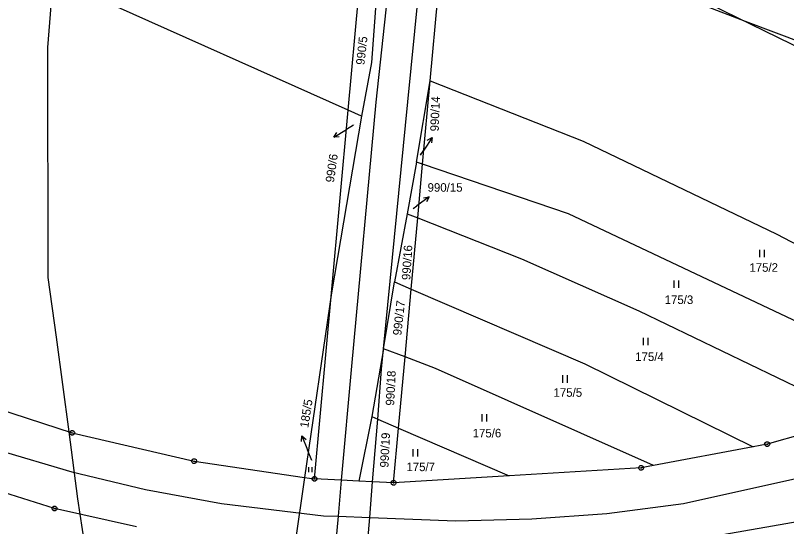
# Model space of a CAD drawing. Extents: x -755359 to -754474, y -1162585 to -1161655.
# Drawn here: x -755164.4 to -755011, y -1162245.9 to -1162144.3 of the extents above; entities that cross this region are included whole.
import ezdxf

# ---------------------------------------------------------------- set-up
doc = ezdxf.new("R2010")
doc.units = 0
for name, color, linetype in [('Vrstva 1', 7, 'Continuous'), ('Vrstva 11', 7, 'Continuous'), ('Vrstva 2', 7, 'Continuous'), ('Vrstva 3', 7, 'Continuous'), ('Vrstva 4', 7, 'Continuous'), ('Vrstva 6', 7, 'Continuous'), ('Vrstva 7', 7, 'Continuous'), ('Vrstva 8', 7, 'Continuous')]:
    doc.layers.add(name, color=color, linetype=linetype)

msp = doc.modelspace()

# ---------------------------------------------------------------- linework, layer by layer
at = {"layer": 'Vrstva 1'}
for p, q in [((-755081.87, -1162157.32), (-755078.18, -1162116.73)), ((-755078.18, -1162116.73), (-754923.5, -1162192.2)), ((-755098.17, -1162163.16), (-755171.47, -1162130.42)), ((-755098.17, -1162163.16), (-755095.99, -1162139.26)), ((-755092.6, -1162141.02), (-755093.55, -1162153.72)), ((-755093.55, -1162153.72), (-755095.52, -1162164.34)), ((-755084.59, -1162173.51), (-755081.87, -1162157.32)), ((-755083.38, -1162173.92), (-755081.87, -1162157.32)), ((-755081.87, -1162157.32), (-755051.44, -1162169.33)), ((-755101.49, -1162199.47), (-755098.17, -1162163.16)), ((-755095.52, -1162164.34), (-755098.17, -1162163.16)), ((-755095.52, -1162164.34), (-755101.49, -1162199.47)), ((-755051.44, -1162169.33), (-755012.93, -1162187.79)), ((-755084.59, -1162173.51), (-755086.46, -1162183.76)), ((-755083.38, -1162173.92), (-755084.59, -1162173.51)), ((-755084.35, -1162184.59), (-755083.38, -1162173.92)), ((-755054.32, -1162183.78), (-755083.38, -1162173.92)), ((-755086.46, -1162183.76), (-755088.99, -1162197.29)), ((-755086.46, -1162183.76), (-755084.35, -1162184.59)), ((-755003.14, -1162207.94), (-755054.32, -1162183.78)), ((-755085.64, -1162198.73), (-755084.35, -1162184.59)), ((-755084.35, -1162184.59), (-755063.67, -1162192.69)), ((-755012.93, -1162187.79), (-754964.26, -1162213.49)), ((-755063.67, -1162192.69), (-755040.35, -1162203.08)), ((-755091.13, -1162210.63), (-755088.99, -1162197.29)), ((-755088.99, -1162197.29), (-755085.64, -1162198.73)), ((-755086.87, -1162212.23), (-755085.64, -1162198.73)), ((-755085.64, -1162198.73), (-755051.1, -1162213.59)), ((-755101.49, -1162199.47), (-755106.85, -1162236.16)), ((-755104.87, -1162236.45), (-755101.49, -1162199.47)), ((-755040.35, -1162203.08), (-754996.22, -1162224.35)), ((-755091.13, -1162210.63), (-755093.47, -1162224.09)), ((-755086.87, -1162212.23), (-755091.13, -1162210.63)), ((-755088.15, -1162226.38), (-755086.87, -1162212.23)), ((-755080.8, -1162214.51), (-755086.87, -1162212.23)), ((-755037.41, -1162233.8), (-755080.8, -1162214.51)), ((-755051.1, -1162213.59), (-755017.58, -1162230.07)), ((-755175.66, -1162219.97), (-755153.09, -1162227.31)), ((-755093.47, -1162224.09), (-755096.04, -1162236.88)), ((-755093.47, -1162224.09), (-755092.31, -1162224.59)), ((-755092.31, -1162224.59), (-755088.15, -1162226.38)), ((-754996.22, -1162224.35), (-755014.83, -1162229.55)), ((-755089.14, -1162237.23), (-755088.15, -1162226.38)), ((-755088.15, -1162226.38), (-755066.18, -1162235.85)), ((-755153.09, -1162227.31), (-755128.84, -1162232.93)), ((-755017.58, -1162230.07), (-755037.41, -1162233.8)), ((-755014.83, -1162229.55), (-755017.58, -1162230.07)), ((-755128.84, -1162232.93), (-755106.85, -1162236.16)), ((-755039.91, -1162234.27), (-755066.18, -1162235.85)), ((-755037.41, -1162233.8), (-755039.91, -1162234.27)), ((-755156.59, -1162242.36), (-755179.53, -1162235.08)), ((-755106.85, -1162236.16), (-755108.91, -1162250.29)), ((-755106.85, -1162236.16), (-755104.87, -1162236.45)), ((-755066.18, -1162235.85), (-755089.14, -1162237.23)), ((-755099.55, -1162236.71), (-755104.87, -1162236.45)), ((-755096.04, -1162236.88), (-755099.55, -1162236.71)), ((-755093.31, -1162237.02), (-755096.04, -1162236.88)), ((-755089.14, -1162237.23), (-755093.31, -1162237.02)), ((-755140.31, -1162246.01), (-755156.59, -1162242.36)), ((-755003.23, -1162244.03), (-755013.79, -1162245.86)), ((-755013.79, -1162245.86), (-755036.82, -1162249.84))]:
    msp.add_line(p, q, dxfattribs=at)
at = {"layer": 'Vrstva 11'}
for p, q in [((-755156.92, -1162136.92), (-755157.97, -1162150.73)), ((-755019.15, -1162145.53), (-755027.45, -1162142.39)), ((-755000.49, -1162152.59), (-755019.15, -1162145.53)), ((-755157.97, -1162150.73), (-755157.96, -1162196.43)), ((-755157.96, -1162196.43), (-755156.26, -1162208.28)), ((-755156.26, -1162208.28), (-755153.77, -1162227.09)), ((-755153.77, -1162227.09), (-755152.01, -1162240.45)), ((-755152.01, -1162240.45), (-755151.54, -1162243.49)), ((-755151.54, -1162243.49), (-755148.61, -1162262.46))]:
    msp.add_line(p, q, dxfattribs=at)
at = {"layer": 'Vrstva 3'}
for p, q in [((-755016.38, -1162190.9), (-755016.38, -1162192.4)), ((-755015.38, -1162192.4), (-755015.38, -1162190.9)), ((-755033.38, -1162197.01), (-755033.38, -1162198.51)), ((-755032.38, -1162198.51), (-755032.38, -1162197.01)), ((-755039.5, -1162208.39), (-755039.5, -1162209.89)), ((-755038.5, -1162209.89), (-755038.5, -1162208.39)), ((-755055.53, -1162215.84), (-755055.53, -1162217.34)), ((-755054.53, -1162217.34), (-755054.53, -1162215.84)), ((-755071.62, -1162223.57), (-755071.62, -1162225.07)), ((-755070.62, -1162225.07), (-755070.62, -1162223.57)), ((-755085.31, -1162230.52), (-755085.31, -1162232.02)), ((-755084.31, -1162232.02), (-755084.31, -1162230.52)), ((-755106.045, -1162234.105), (-755106.045, -1162235.11)), ((-755105.375, -1162235.11), (-755105.375, -1162234.105))]:
    msp.add_line(p, q, dxfattribs=at)
at = {"layer": 'Vrstva 4'}
for p, q in [((-755087.37, -1162112.06), (-755092.67, -1162161.58)), ((-755086.32, -1162161.53), (-755081.63, -1162114.72)), ((-755092.67, -1162161.58), (-755097.54, -1162214.06)), ((-755091.13, -1162210.63), (-755086.32, -1162161.53)), ((-755091.52, -1162214.66), (-755091.13, -1162210.63)), ((-755097.54, -1162214.06), (-755099.55, -1162236.71)), ((-755092.31, -1162224.59), (-755091.52, -1162214.66)), ((-755093.31, -1162237.02), (-755092.31, -1162224.59)), ((-755099.55, -1162236.71), (-755100.18, -1162243.88)), ((-755093.88, -1162244.12), (-755093.31, -1162237.02)), ((-755100.18, -1162243.88), (-755100.83, -1162251.16)), ((-755094.25, -1162248.72), (-755093.88, -1162244.12))]:
    msp.add_line(p, q, dxfattribs=at)
at = {"layer": 'Vrstva 6'}
for p, q in [((-755168.39, -1162230.54), (-755153.14, -1162235.03)), ((-755031.48, -1162241.38), (-754992.46, -1162232.61)), ((-755153.14, -1162235.03), (-755138.48, -1162238.56)), ((-755138.48, -1162238.56), (-755123.39, -1162241.32)), ((-755123.39, -1162241.32), (-755103.11, -1162243.77)), ((-755046.74, -1162243.36), (-755031.48, -1162241.38)), ((-755103.11, -1162243.77), (-755100.18, -1162243.88)), ((-755100.18, -1162243.88), (-755093.88, -1162244.12)), ((-755061.62, -1162244.43), (-755046.74, -1162243.36)), ((-755093.88, -1162244.12), (-755076.74, -1162244.78)), ((-755076.74, -1162244.78), (-755061.62, -1162244.43))]:
    msp.add_line(p, q, dxfattribs=at)
at = {"layer": 'Vrstva 7'}
for p, q in [((-755101.061, -1162168.536), (-755098.49, -1162166.99)), ((-755097.12, -1162166.15), (-755098.49, -1162166.99)), ((-755081.486, -1162168.584), (-755083.12, -1162171.1)), ((-755083.77, -1162172.11), (-755083.12, -1162171.1)), ((-755082.063, -1162180.396), (-755084.49, -1162182.16)), ((-755085.23, -1162182.69), (-755084.49, -1162182.16)), ((-755107.404, -1162227.908), (-755106.28, -1162230.69)), ((-755105.43, -1162232.8), (-755106.28, -1162230.69))]:
    msp.add_line(p, q, dxfattribs=at)
for points in [[(-755099.947, -1162168.449), (-755101.061, -1162168.536), (-755100.462, -1162167.592)], [(-755082.45, -1162169.15), (-755081.486, -1162168.584), (-755081.611, -1162169.695)], [(-755083.166, -1162180.58), (-755082.063, -1162180.396), (-755082.578, -1162181.388)], [(-755107.493, -1162229.023), (-755107.404, -1162227.908), (-755106.566, -1162228.648)]]:
    msp.add_lwpolyline(points, dxfattribs=at)
at = {"layer": 'Vrstva 8'}
for p, q in [((-755153.21, -1162227.31), (-755152.97, -1162227.31)), ((-755014.95, -1162229.55), (-755014.71, -1162229.55)), ((-755128.96, -1162232.93), (-755128.72, -1162232.93)), ((-755040.03, -1162234.27), (-755039.79, -1162234.27)), ((-755104.99, -1162236.45), (-755104.75, -1162236.45)), ((-755089.26, -1162237.23), (-755089.02, -1162237.23)), ((-755156.71, -1162242.36), (-755156.47, -1162242.36))]:
    msp.add_line(p, q, dxfattribs=at)
for points in [[(-755152.94, -1162226.83), (-755152.69, -1162227.01), (-755152.59, -1162227.3), (-755152.69, -1162227.59), (-755152.94, -1162227.77), (-755153.25, -1162227.77), (-755153.5, -1162227.59), (-755153.6, -1162227.3), (-755153.5, -1162227.01), (-755153.25, -1162226.83)], [(-755014.68, -1162229.07), (-755014.43, -1162229.25), (-755014.33, -1162229.54), (-755014.43, -1162229.83), (-755014.68, -1162230.01), (-755014.99, -1162230.01), (-755015.24, -1162229.83), (-755015.34, -1162229.54), (-755015.24, -1162229.25), (-755014.99, -1162229.07)], [(-755128.69, -1162232.45), (-755128.44, -1162232.63), (-755128.34, -1162232.92), (-755128.44, -1162233.21), (-755128.69, -1162233.39), (-755129, -1162233.39), (-755129.25, -1162233.21), (-755129.35, -1162232.92), (-755129.25, -1162232.63), (-755129, -1162232.45)], [(-755039.76, -1162233.79), (-755039.51, -1162233.97), (-755039.41, -1162234.26), (-755039.51, -1162234.55), (-755039.76, -1162234.73), (-755040.07, -1162234.73), (-755040.32, -1162234.55), (-755040.42, -1162234.26), (-755040.32, -1162233.97), (-755040.07, -1162233.79)], [(-755104.72, -1162235.97), (-755104.47, -1162236.15), (-755104.37, -1162236.44), (-755104.47, -1162236.73), (-755104.72, -1162236.91), (-755105.03, -1162236.91), (-755105.28, -1162236.73), (-755105.38, -1162236.44), (-755105.28, -1162236.15), (-755105.03, -1162235.97)], [(-755088.99, -1162236.75), (-755088.74, -1162236.93), (-755088.64, -1162237.22), (-755088.74, -1162237.51), (-755088.99, -1162237.69), (-755089.3, -1162237.69), (-755089.55, -1162237.51), (-755089.65, -1162237.22), (-755089.55, -1162236.93), (-755089.3, -1162236.75)], [(-755156.44, -1162241.88), (-755156.19, -1162242.06), (-755156.09, -1162242.35), (-755156.19, -1162242.64), (-755156.44, -1162242.82), (-755156.75, -1162242.82), (-755157, -1162242.64), (-755157.1, -1162242.35), (-755157, -1162242.06), (-755156.75, -1162241.88)]]:
    msp.add_lwpolyline(points, close=True, dxfattribs=at)

# ---------------------------------------------------------------- texts
at = {"layer": 'Vrstva 2'}
for s, height, rotation, p in [('990/5', 1.7, 83.70913, (-755094.954, -1162154.244)), ('990/14', 0.1, 83.70913, (-755083.768, -1162172.096)), ('990/16', 1.7, 86.40204, (-755085.835, -1162196.983)), ('990/17', 1.7, 83.70913, (-755087.614, -1162208.014)), ('990/18', 1.7, 87.31877, (-755089.039, -1162221.923)), ('990/19', 1.7, 87.31877, (-755090.169, -1162234.243))]:
    msp.add_text(s, height=height, rotation=rotation, dxfattribs=at).set_placement(p)
for s, height, p in [('990/6', 0.1, (-755097.106, -1162166.15)), ('990/15', 0.1, (-755085.216, -1162182.69)), ('175/2', 1.7, (-755018.367, -1162195.29)), ('175/3', 1.7, (-755035.217, -1162201.7)), ('175/4', 1.7, (-755041.077, -1162213.03)), ('175/5', 1.7, (-755057.327, -1162220.14)), ('175/6', 1.7, (-755073.417, -1162228.21)), ('185/5', 0.1, (-755105.407, -1162232.8)), ('175/7', 1.7, (-755086.597, -1162234.92))]:
    msp.add_text(s, height=height, dxfattribs=at).set_placement(p)
at = {"layer": 'Vrstva 7'}
for s, rotation, p in [('990/14', 88.00632, (-755080.172, -1162167.413)), ('990/6', 81.99026, (-755101.024, -1162177.625)), ('185/5', 81.01623, (-755106.129, -1162226.412))]:
    msp.add_text(s, height=1.7, rotation=rotation, dxfattribs=at).set_placement(p)
msp.add_text('990/15', height=1.7, dxfattribs=at).set_placement((-755082.383, -1162179.38))

doc.saveas('drawing.dxf')
